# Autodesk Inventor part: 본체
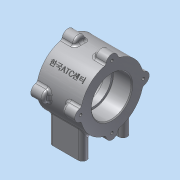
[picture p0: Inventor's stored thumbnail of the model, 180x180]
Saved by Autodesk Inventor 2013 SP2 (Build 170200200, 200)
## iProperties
Created: 2015-03
Part Number: 본체
Material: 알루미늄 6061
Document SubType Name: Modeling
Designer: dgall
Density: 2.71 g/cm^3
Mass: 450.776 g
Surface Area: 332.735 cm^2
Volume: 166.338 cm^3
Author: dgall
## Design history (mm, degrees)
sketch "스케치1"
  geometry: C1 r 37 at (0, 0); 1 further point
  constraints: 1 centre point, 1 coincident
  dimensions: "d0" = 74 diameter of C1
extrude "돌출1" new body sketch "스케치1" stored distance "d2" = 52; taper "d3" = 0 deg
sketch "스케치2"
  geometry: A1 r 37 centre (0, 0) between (0, 37) and (-6.969, 36.338) reference; A2 r 7 centre (0, 37) between (6.969, 36.338) and (-6.969, 36.338)
  constraints: 5 point on circle, 1 centre point, 1 vertical alignment
  dimensions: "d4" = 7 radius of A2
extrude "돌출2" join sketch "스케치2" distance "d6" = 15; taper "d7" = 0 deg
sketch "스케치3"
  geometry: L1 (-19, -20)-(-29, -20); L2 (-29, -20)-(-29, 20); L3 (-29, 20)-(-19, 20); L4 (-19, 20)-(-19, -20); 3 further points
  constraints: 8 end point, 2 midpoint, 2 parallel, 1 horizontal, 1 horizontal alignment, 1 perpendicular
  dimensions: "d11" = 10 distance of L1.start L1.end; "d13" = 40 distance of L1.end L2.end; "d14" = 24 horizontal distance of point (-24, 20) point (0, 0)
extrude "돌출3" join sketch "스케치3" distance "d15" = 56; taper "d16" = 0 deg
sketch "스케치4"
  geometry: L1 (36.338, 26)-(6.969, 26) reference; L2 (6.969, -26)-(36.338, -26) reference; L3 (7, 26)-(-7, 26) reference; L4 (7, -26)-(-7, -26) reference; L5 (0, 26)-(0, -26); L6 (23.5, 26)-(23.5, 4); L7 (23.5, 4)-(21, 4); L8 (21, 4)-(21, -4); L9 (21, -4)-(23.5, -4); L10 (23.5, -4)-(23.5, -26); 3 further points
  constraints: 12 end point, 3 parallel, 2 midpoint, 2 perpendicular, 2 point on line, 1 collinear, 1 vertical alignment
  dimensions: "d17" = 47 diameter of L6 L5; "d19" = 47 diameter of L10 L5; "d20" = 42 diameter of L8 L5; "d21" = 22 distance of L6.start L6.end; "d22" = 22 distance of L9.end L10.end
revolve "회전1" sketch "스케치4" stored, may be unused: angle "d23" = 90 deg
hole "구멍1" diameter "d26" = 3.242; stored, may be unused: countersink angle "d30" = 90 deg, drill point angle "d32" = 118 deg; dims "d24" = 10, "d25" = 10, "d27" = 8, "d28" = 4, "d29" = 2, "d31" = 11
sketch "스케치5"
  geometry: L1 (29, 20)-(19, 20) reference; 3 further points
  constraints: 1 midpoint, 1 vertical alignment
  dimensions: "d36" = 5 distance from line of point (24, 15) L1
hole "구멍2" sketch "스케치5" at (24, 15) diameter "d37" = 4.134; stored, may be unused: countersink angle "d41" = 90 deg, drill point angle "d43" = 118 deg; dims "d38" = 6, "d39" = 4, "d40" = 2, "d42" = 8
sketch "스케치6"
  geometry: L1 (0, 0)-(-26.163, 26.163); L2 (0, 0)-(-44, 0); C1 r 1.621 at (37, 0) reference; C2 r 1.621 at (0, -37) reference; C3 r 1.621 at (-37, 0) reference; C4 r 1.621 at (0, 37) reference; C5 r 23.5 at (0, 0) reference; A1 r 37 centre (0, 0) between (-6.969, 36.338) and (-36.338, 6.969) reference; A2 r 7 centre (-37, 0) between (-36.338, 6.969) and (-36.338, -6.969) reference; A3 r 37 centre (0, 0) between (-36.338, -6.969) and (-6.969, -36.338) reference; A4 r 7 centre (0, -37) between (-6.969, -36.338) and (6.969, -36.338) reference; A5 r 37 centre (0, 0) between (6.969, -36.338) and (36.338, -6.969) reference; A6 r 7 centre (37, 0) between (36.338, -6.969) and (36.338, 6.969) reference; A7 r 37 centre (0, 0) between (36.338, 6.969) and (6.969, 36.338) reference; A8 r 7 centre (0, 37) between (6.969, 36.338) and (-6.969, 36.338) reference
  constraints: 4 end point, 2 point on circle
  dimensions: "d46" = 45 deg angle of L1 L2
node "작업 평면3"
sketch "스케치7"
  geometry: L1 (20.767, 0)-(-20.767, 0) reference; 3 further points
  constraints: 1 coincident, 1 midpoint, 1 vertical alignment, 1 other
feature "엠보싱1" sketch "스케치7" dims "d47" = 0.5, "d48" = 0
fillet "모깎기1" dims "d49" = 5, "d50" = 3, "d52" = 0.3
fillet "모깎기2" dims "d51" = 3
chamfer "모따기1" distance "d53" = 1; stored, may be unused: second distance "d54" = 2, angle "d55" = 45 deg
node "솔리드1"
pattern_circular "원형 패턴1" dims angle "d9" = 360 deg
mirror "대칭1"
mirror "대칭2"
pattern_circular "원형 패턴2" dims angle "d34" = 360 deg
mirror "대칭3"
mirror "대칭4"
mirror "대칭5"
